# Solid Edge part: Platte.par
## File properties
Sűrűség: 0,000 kg/m^3
Pontosság: 0,990
Author: bmolnar
Last saved by: bmolnar
Revision: 76
Username: bmolnar
Dokumentum tartalom típus: 0
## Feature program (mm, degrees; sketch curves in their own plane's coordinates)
base feature "unnamed BaseFeature 1"
thread "unnamed Thread 1"
thread "unnamed Thread 2"
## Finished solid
Body 1: solid body, 157 faces, 378 edges, 220 vertices, 2 internal voids.
  Faces by surface: plane 74, cylinder 60, cone 20, torus 3
  Edges by curve: line 220, circle 140, spline 18
Bounding box of the edges (mm; curved faces can reach further): 65.400 x 65.400 x 12.000, from (-32.7, -32.7, 102.95) to (32.7, 32.7, 114.95).
Cylindrical faces by radius (mm): R0.15 x18, R0.2 x2, R0.25 x20, R2.4585 x2, R3 x2, R3.65 x2, R5 x2, R5.25 x2, R5.5 x2, R6.5 x2, R8 x5, R11 x1
Conical faces (half-angle, radius in mm at the cone's reference point): 45 deg R2.7085 x4, 45 deg R3.15 x4, 45 deg R3.7 x2, 45 deg R5.4 x2, 45 deg R5.65 x4, 45 deg R11.15 x1, 60 deg R1.1547 x2, 60 deg R2.0207 x1
Toroidal faces (ring radius, tube radius in mm): R4.4 r0.6 x2, R7 r1 x1
Planar faces by outward normal: +x 11, +y 15, +z 7, -x 11, -y 15, -z 3, oblique 12
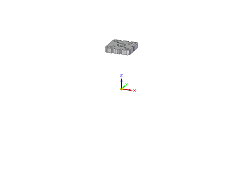
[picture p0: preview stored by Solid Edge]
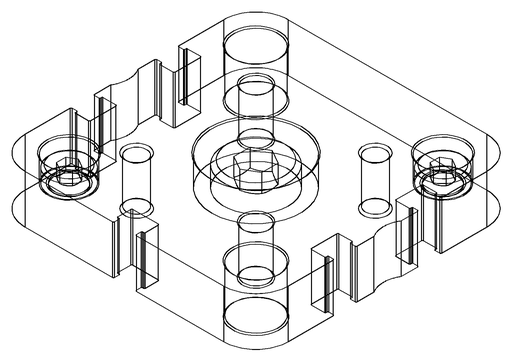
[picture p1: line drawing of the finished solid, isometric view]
